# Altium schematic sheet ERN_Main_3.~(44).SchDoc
size A; SheetNumber: 3; SheetTotal: 4; SPICEModelCacheXVWYUVSQ: <root> / <DocumentId>XVWYUVSQ</DocumentId> / <CacheFrame Number="0"> / <Model Name="irf1010" Kind="CKT"> / <Text>*IRF1010 MCE 4-2-96 / *55V  75A .014 ohm HEXFET pkg:TO-220 2,1,3 / .SUBCKT IRF1010  10 20 40 40 / M1   1  2  3  3  DMOS L=1U W=1U / RD  10  1  5.65M / RS  30  3  1.35M / RG  20  2  12.1 / CGS  2  3  2.15N / EGD 12  0  2  1  1 / VFB 14  0  0 / FFB  2  1  VFB  1 / CGD 13 14  4.49N / R1  13  0  1 / D1  12 13  DLIM / DDG 15 14  DCGD / R2  12 15  1 / D2  15  0  DLIM / DSD  3 10  DSUB / LS  30 40  7.5N / .MODEL DMOS NMOS (LEVEL=3 THETA=60M VMAX=114K ETA=2M VTO=3 KP=19.4) / .MODEL DCGD D (CJO=4.49N VJ=.6 M=.68) / .MODEL DSUB D (IS=311N N=1.5 RS=8.67M BV=55 CJO=4.08N VJ=.8 M=.42 TT=100N) / .MODEL DLIM D (IS=100U) / .ENDS IRF1010</Text> / </Model> / <Model Name="1n4148" Kind="MDL"> / <Text>.model 1N4148  D(Is=0.1p Rs=16 CJO=2p Tt=12n Bv=100 Ibv=0.1p)</Text> / </Model> / <Model Name="npn" Kind="MDL"> / <Text>*Default NPN BJT / *NPN Trans Pinout: C,B,E / .MODEL NPN NPN()</Text> / </Model> / </CacheFrame> / </root>
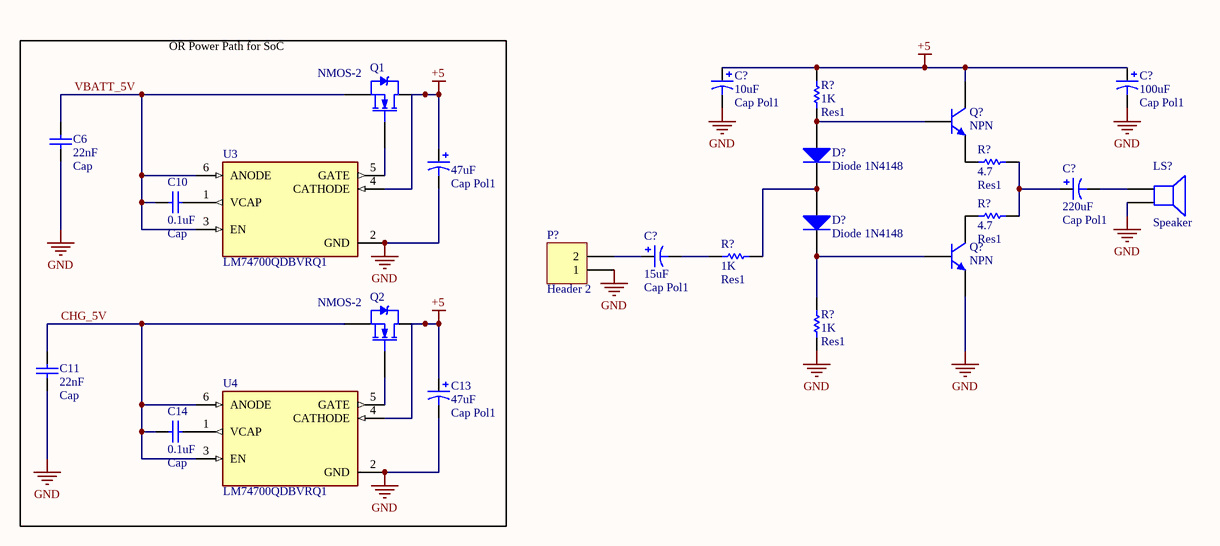
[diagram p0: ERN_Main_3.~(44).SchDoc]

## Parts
(Parts that share a designator on the sheet are numbered #1, #2 ... from top to bottom, then left to right.)
?  Cap Pol1  value 47uF  [RB7.6-15]
C6  Cap  value 22nF  [RAD-0.3]
C10  Cap  value 0.1uF  [RAD-0.3]
C11  Cap  value 22nF  [RAD-0.3]
C13  Cap Pol1  value 47uF  [RB7.6-15]
C14  Cap  value 0.1uF  [RAD-0.3]
C?#1  Cap Pol1  value 10uF  [RB7.6-15]
C?#2  Cap Pol1  value 100uF  [RB7.6-15]
C?#3  Cap Pol1  value 220uF  [RB7.6-15]
C?#4  Cap Pol1  value 15uF  [RB7.6-15]
D?#1  Diode 1N4148  [DO-35]
D?#2  Diode 1N4148  [DO-35]
LS?  Speaker  [PIN2]
P?  Header 2  [HDR1X2]
Q1  NMOS-2  [TO-220AB]
Q2  NMOS-2  [TO-220AB]
Q?#1  NPN  [TO-226-AA]
Q?#2  NPN  [TO-226-AA]
R?#1  Res1  value 1K  [AXIAL-0.3]
R?#2  Res1  value 4.7  [AXIAL-0.3]
R?#3  Res1  value 4.7  [AXIAL-0.3]
R?#4  Res1  value 1K  [AXIAL-0.3]
R?#5  Res1  value 1K  [AXIAL-0.3]
U3  LM74700QDBVRQ1  [SOT95P280X145-6N]
U4  LM74700QDBVRQ1  [SOT95P280X145-6N]

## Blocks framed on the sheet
OR Power Path for SoC: ? C6 C10 C11 C13 C14 Q1 Q2 U3 U4

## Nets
+5: ?.1 C13.1 C?#1.1 C?#2.1 Q1.2(D) Q2.2(D) Q?#1.1(C) R?#1.2 U3.4(CATHODE) U4.4(CATHODE)
GND: ?.2 C6.1 C11.1 C13.2 C?#1.2 C?#2.2 LS?.2 P?.1 Q?#2.3(E) R?#5.1 U3.2(GND) U4.2(GND)
CHG_5V: C11.2 C14.2 Q2.3(S) U4.3(EN) U4.6(ANODE)
VBATT_5V: C6.2 C10.2 Q1.3(S) U3.3(EN) U3.6(ANODE)
NetC10_1: C10.1 U3.1(VCAP)
NetC14_1: C14.1 U4.1(VCAP)
NetC?#3_1: C?#3.1 R?#2.2 R?#3.2
NetC?#3_2: C?#3.2 LS?.1
NetC?#4_1: C?#4.1 P?.2
NetC?#4_2: C?#4.2 R?#4.1
NetD?#1_1: D?#1.1(A) Q?#1.2(B) R?#1.1
NetD?#1_2: D?#1.2(K) D?#2.1(A) R?#4.2
NetD?#2_2: D?#2.2(K) Q?#2.2(B) R?#5.2
NetQ1_1: Q1.1(G) U3.5(GATE)
NetQ2_1: Q2.1(G) U4.5(GATE)
NetQ?#1_3: Q?#1.3(E) R?#2.1
NetQ?#2_1: Q?#2.1(C) R?#3.1

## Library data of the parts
? C13 C?#1-C?#4 = Cap Pol1: Polarized Capacitor (Radial)
C6 C10 C11 C14 = Cap: Capacitor
D?#1 D?#2 = Diode 1N4148: High Conductance Fast Diode
LS? = Speaker: Loudspeaker
P? = Header 2: Header, 2-Pin
Q1 Q2 = NMOS-2: N-Channel Power MOSFET; Note: Pin 2 is electrically connected to pin 4.
Q?#1 Q?#2 = NPN: NPN Bipolar Transistor
R?#1-R?#5 = Res1: Resistor
U3 U4 = LM74700QDBVRQ1: 3.2-V to 65-V, 80-uA IQ automotive ideal diode controller; MF: Texas Instruments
